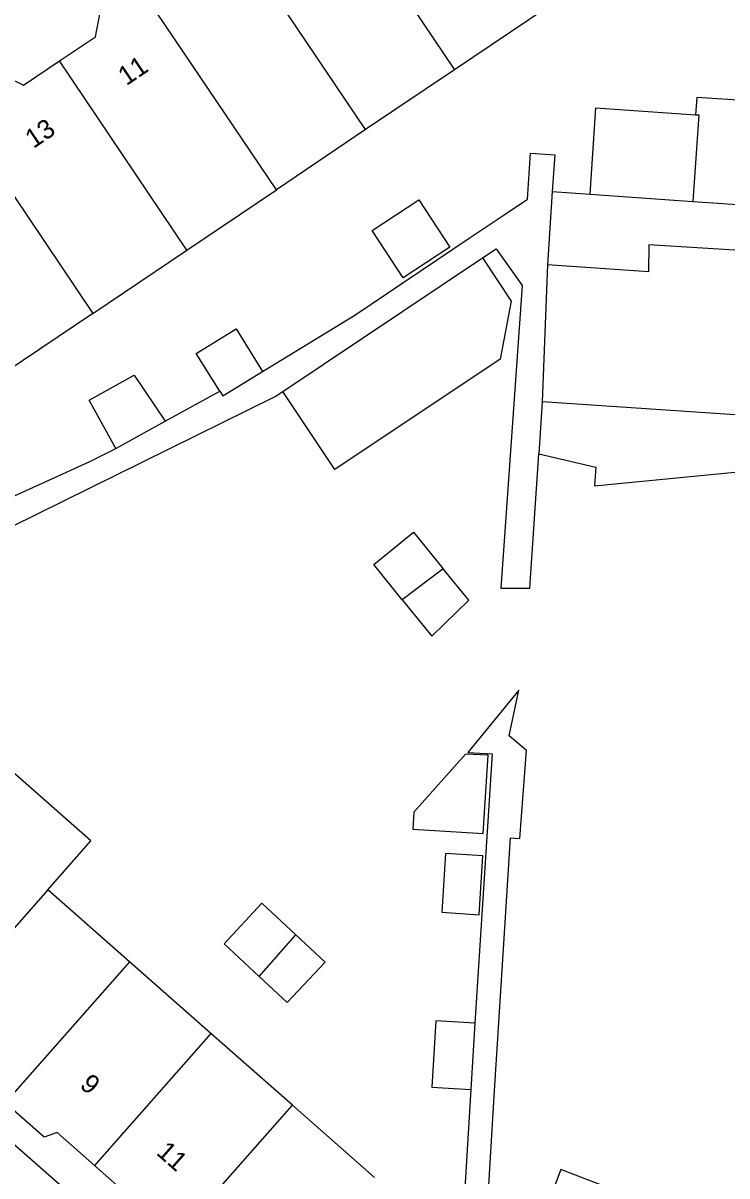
# Model space of a CAD drawing. Extents: x 159961 to 160856, y 382704 to 383353.
# Drawn here: x 160517.5 to 160554.4, y 382840.4 to 382900.9 of the extents above; entities that cross this region are included whole.
import ezdxf

# ---------------------------------------------------------------- set-up
doc = ezdxf.new("R2010")
doc.units = 0
for name, color, linetype in [('IMGEO_Pand', 7, 'Continuous'), ('IMGEO_Pand_nummerreeks', 7, 'Continuous'), ('IMGEO_Voetpad_open', 7, 'Continuous')]:
    doc.layers.add(name, color=color, linetype=linetype)

msp = doc.modelspace()

# ---------------------------------------------------------------- linework, layer by layer
at = {"layer": 'IMGEO_Pand'}
for points in [[(160533.02, 382909.012), (160540.146, 382898.432)], [(160535.484, 382895.292), (160528.81, 382905.202)], [(160519.418, 382898.898), (160521.302, 382900.167), (160521.535, 382901.36), (160523.637, 382902.776)], [(160530.802, 382892.138), (160523.637, 382902.776)], [(160545.006, 382901.706), (160540.146, 382898.432)], [(160514.463, 382895.591), (160514.863, 382895.86), (160515.1, 382897.078), (160516.596, 382898.086), (160517.533, 382897.628), (160519.418, 382898.898)], [(160526.103, 382888.972), (160519.418, 382898.898)], [(160540.146, 382898.432), (160535.484, 382895.292)], [(160558.833, 382896.589), (160552.857, 382896.986), (160552.795, 382896.076)], [(160547.258, 382891.902), (160547.567, 382896.433), (160552.795, 382896.076)], [(160552.795, 382896.076), (160552.96, 382896.065), (160552.651, 382891.528)], [(160514.463, 382895.591), (160521.162, 382885.644)], [(160535.484, 382895.292), (160530.802, 382892.138)], [(160526.103, 382888.972), (160530.802, 382892.138)], [(160545.277, 382892.039), (160545.028, 382888.202)], [(160545.277, 382892.039), (160547.258, 382891.902)], [(160535.829, 382890.004), (160538.277, 382891.609), (160539.905, 382889.126), (160537.457, 382887.521), (160535.829, 382890.004)], [(160547.258, 382891.902), (160552.651, 382891.528)], [(160552.651, 382891.528), (160556.037, 382891.294), (160558.466, 382891.163)], [(160558.275, 382888.339), (160555.958, 382888.484), (160555.97, 382888.904), (160550.348, 382889.255), (160550.318, 382887.835), (160545.028, 382888.202)], [(160521.162, 382885.644), (160526.103, 382888.972)], [(160531.13, 382881.556), (160541.609, 382888.558)], [(160541.609, 382888.558), (160543.124, 382886.291), (160542.541, 382883.247), (160533.87, 382877.453), (160531.13, 382881.556)], [(160521.162, 382885.644), (160516.566, 382882.547)], [(160527.838, 382881.564), (160526.597, 382883.553), (160528.685, 382884.84), (160530.072, 382882.6)], [(160522.369, 382878.563), (160520.976, 382881.101), (160523.346, 382882.401), (160524.969, 382879.99)], [(160527.838, 382881.564), (160527.991, 382881.318), (160530.072, 382882.6)], [(160544.75, 382881.002), (160544.567, 382878.278)], [(160557.721, 382880.127), (160544.75, 382881.002)], [(160522.369, 382878.563), (160524.969, 382879.99)], [(160544.567, 382878.278), (160547.557, 382877.585), (160547.49, 382876.598), (160557.549, 382877.583), (160557.348, 382874.613)], [(160537.407, 382870.616), (160535.909, 382872.463), (160538.001, 382874.161), (160539.551, 382872.251)], [(160539.551, 382872.251), (160537.407, 382870.616)], [(160537.407, 382870.616), (160538.954, 382868.71), (160540.891, 382870.599), (160539.551, 382872.251)], [(160540.715, 382862.526), (160538.011, 382859.479), (160537.953, 382858.587), (160541.655, 382858.348), (160541.921, 382862.467), (160540.715, 382862.526)], [(160518.81, 382855.398), (160521.07, 382857.963), (160516.785, 382861.739)], [(160539.476, 382854.22), (160541.435, 382854.093), (160541.634, 382857.175), (160539.675, 382857.302), (160539.476, 382854.22)], [(160518.81, 382855.398), (160512.718, 382848.485)], [(160523.096, 382851.622), (160518.81, 382855.398)], [(160531.823, 382853.031), (160530.038, 382854.694), (160528.056, 382852.568), (160529.902, 382850.848)], [(160529.902, 382850.848), (160531.823, 382853.031)], [(160529.902, 382850.848), (160531.37, 382849.48), (160533.351, 382851.608), (160531.823, 382853.031)], [(160523.096, 382851.622), (160516.573, 382844.221)], [(160527.361, 382847.865), (160523.096, 382851.622)], [(160541.209, 382848.393), (160539.171, 382848.515), (160538.963, 382845.045), (160541.001, 382844.923)], [(160527.361, 382847.865), (160521.254, 382840.936)], [(160531.64, 382844.097), (160527.361, 382847.865)], [(160541.209, 382848.393), (160541.001, 382844.923)], [(160521.254, 382840.936), (160519.305, 382842.654), (160518.615, 382842.422), (160516.573, 382844.221)], [(160525.119, 382836.698), (160531.64, 382844.097)], [(160535.945, 382840.304), (160531.64, 382844.097)], [(160525.119, 382836.698), (160523.063, 382838.509), (160523.205, 382839.218), (160521.254, 382840.936)], [(160545.118, 382839.099), (160545.323, 382838.171), (160547.55, 382837.321), (160548.449, 382839.678), (160545.734, 382840.714), (160545.118, 382839.099)]]:
    msp.add_lwpolyline(points, dxfattribs=at)
at = {"layer": 'IMGEO_Voetpad_open'}
for points in [[(160530.072, 382882.6), (160534.916, 382885.552), (160540.916, 382889.594), (160542.649, 382890.752), (160543.984, 382891.645), (160544.141, 382894.061), (160545.403, 382893.979), (160545.277, 382892.039)], [(160541.609, 382888.558), (160542.334, 382889.043), (160543.703, 382887.115), (160542.574, 382871.236), (160544.094, 382871.236), (160544.567, 382878.278)], [(160545.028, 382888.202), (160545.001, 382887.778), (160544.75, 382881.002)], [(160504.629, 382867.246), (160509.915, 382871.014), (160530.736, 382881.292), (160531.13, 382881.556)], [(160524.969, 382879.99), (160527.838, 382881.564)], [(160516.667, 382875.901), (160520.974, 382877.863), (160522.369, 382878.563)], [(160540.954, 382835.892), (160541.774, 382836.979), (160542.245, 382844.848), (160542.797, 382853.681), (160543.084, 382858.124), (160543.572, 382858.092), (160543.928, 382862.713), (160543.013, 382863.485), (160543.52, 382865.882), (160540.854, 382862.61), (160542.119, 382862.528), (160541.209, 382848.393)], [(160493.381, 382860.512), (160494.549, 382861.818), (160495.05, 382861.37), (160552.075, 382811.222)], [(160541.001, 382844.923), (160540.552, 382837.429), (160540.016, 382836.718)]]:
    msp.add_lwpolyline(points, dxfattribs=at)

# ---------------------------------------------------------------- texts
at = {"layer": 'IMGEO_Pand_nummerreeks'}
for s, rotation, p in [('11', 34.0635, (160522.928, 382897.571)), ('13', 34.0635, (160518.055, 382894.277)), ('9', 318.67347, (160520.432, 382845.076)), ('11', 318.67347, (160524.452, 382841.543))]:
    msp.add_text(s, height=1, rotation=rotation, dxfattribs=at).set_placement(p)

doc.saveas('drawing.dxf')
